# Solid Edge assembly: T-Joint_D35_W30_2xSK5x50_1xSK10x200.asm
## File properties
Author: fknapp
Template: iso metric assembly.asm
Last saved by: fknapp
Revision: 5
Application: Solid Edge
Username: fknapp
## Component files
T-Joint_D35_W30.par
SK Schraube 5x50_ohne_Gewinde.par
SK Schraube 10x200_ohne_Gewinde_22042020.par
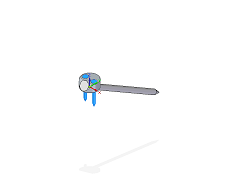
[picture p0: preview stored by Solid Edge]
